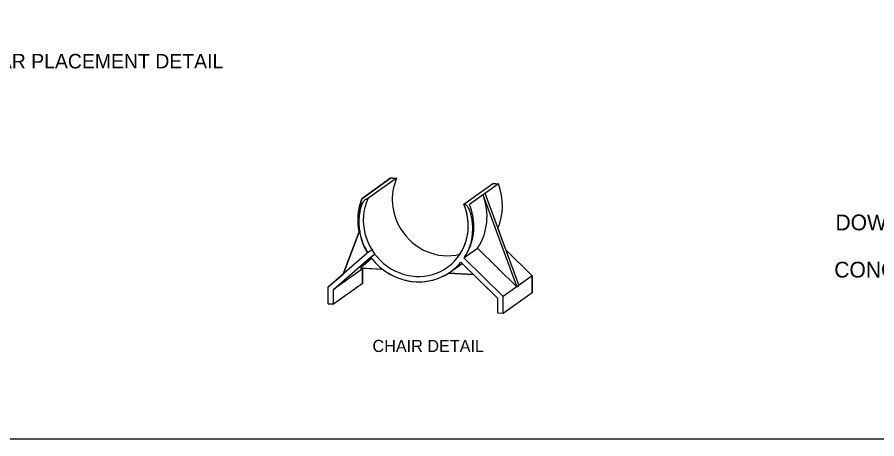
# Model space of a CAD drawing. Extents: x 99862 to 104211, y 98939 to 105076.
# Drawn here: x 101295 to 102716, y 103000 to 103696 of the extents above; entities that cross this region are included whole.
import ezdxf

# ---------------------------------------------------------------- set-up
doc = ezdxf.new("R2010")
doc.units = 0
for name, color, linetype in [('Level 1', 7, 'Continuous'), ('Level 15', 7, 'Continuous'), ('Level 16', 7, 'Continuous'), ('Level 20', 7, 'Continuous'), ('Level 62', 7, 'Continuous')]:
    doc.layers.add(name, color=color, linetype=linetype)

msp = doc.modelspace()

# ---------------------------------------------------------------- linework, layer by layer
at = {"layer": 'Level 1'}
msp.add_lwpolyline([(99862, 102999.5), (103151, 102999.5), (103151, 105075.5), (99862, 105075.5)], close=True, dxfattribs=at)
at = {"layer": 'Level 15'}
msp.add_line((102121.2, 103250.4), (102124.4, 103252.7), dxfattribs=at)
at = {"layer": 'Level 16'}
for p, q in [((101913.2, 103430.3), (101865.3, 103396)), ((101922.6, 103429.8), (101874.7, 103395.5)), ((102033.7, 103386.8), (102081.6, 103421.1)), ((102091, 103420.6), (102043.1, 103386.3)), ((102069, 103403.8), (102124.4, 103252.7)), ((102065.8, 103401.5), (102121.2, 103250.4)), ((101860.7, 103341.5), (101834, 103271.5)), ((101809.6, 103250.2), (101874.5, 103306.9)), ((101874.5, 103306.9), (101881.5, 103311.8)), ((101879.6, 103299.4), (101886.6, 103304.3)), ((102033.9, 103298.2), (102056.3, 103314.2)), ((102121.2, 103250.4), (102056.3, 103314.2)), ((102146.7, 103268.7), (102102.6, 103312)), ((101818.3, 103245.8), (101879.6, 103299.4)), ((101881.3, 103297.3), (101862.6, 103281)), ((102011.8, 103275.4), (102031, 103289.1)), ((102090.1, 103231), (102028.8, 103291.3)), ((102098.8, 103234.5), (102033.9, 103298.2)), ((101866.2, 103280.1), (101818.3, 103245.8)), ((101900, 103279), (101862.6, 103281)), ((101866.2, 103280.1), (101867, 103280.8)), ((101866.2, 103256), (101866.2, 103280.1)), ((102008.5, 103273.1), (102049.6, 103270.8)), ((102146.7, 103268.7), (102098.8, 103234.5)), ((102146.7, 103240.7), (102146.7, 103268.7)), ((101809.6, 103222.3), (101809.6, 103250.2)), ((101866.2, 103256), (101818.3, 103221.8)), ((101818.3, 103221.8), (101818.3, 103245.8)), ((102146.7, 103240.7), (102098.8, 103206.5)), ((102098.8, 103206.5), (102098.8, 103234.5)), ((101809.6, 103222.3), (101818.3, 103221.8)), ((102090.1, 103207), (102090.1, 103231)), ((102098.8, 103206.5), (102090.1, 103207))]:
    msp.add_line(p, q, dxfattribs=at)
for points in [[(101865.3, 103396), (101913.2, 103430.3)], [(102033.7, 103386.8), (102081.6, 103421.1)], [(102089.8, 103347), (102102.6, 103312), (102146.7, 103268.7), (102146.7, 103240.7), (102098.8, 103206.5), (102090.1, 103207), (102090.1, 103231), (102049.6, 103270.8), (102008.5, 103273.1)], [(101900, 103279), (101867, 103280.8), (101866.2, 103280.1), (101866.2, 103256), (101818.3, 103221.8), (101809.6, 103222.3), (101809.6, 103250.2), (101834, 103271.5), (101860.7, 103341.5)]]:
    msp.add_lwpolyline(points, dxfattribs=at)
for centre, major_axis, start_param, end_param in [((102002.1, 103390.1), (52.3, -73.2), 3.653116, 4.644013), ((102002.1, 103390.1), (52.3, -73.2), 3.653116, 4.644013), ((102002.1, 103390.1), (57.6, -80.5), 0.51692, 1.295209), ((102002.1, 103390.1), (57.6, -80.5), 0.51692, 1.295209), ((101979.8, 103374.2), (-57.6, 80.5), 4.428217, 4.436802), ((101954.2, 103355.9), (-52.3, 73.2), 0.511524, 4.47615), ((101976.6, 103371.9), (-57.6, 80.5), 3.485253, 4.436802), ((101954.2, 103355.9), (-52.3, 73.2), 3.495016, 4.47615), ((102002.1, 103390.1), (52.3, -73.2), 4.644013, 5.929762), ((102002.1, 103390.1), (52.3, -73.2), 4.644013, 5.929762), ((101976.6, 103371.9), (-57.6, 80.5), 3.482403, 3.485253), ((101954.2, 103355.9), (-57.6, 80.5), 1.596779, 3.390895), ((101954.2, 103355.9), (-57.6, 80.5), 1.88936, 3.098314)]:
    msp.add_ellipse(centre, major_axis=major_axis, ratio=0.944998, start_param=start_param, end_param=end_param, dxfattribs=at)
for points, degree in [([(101913.2, 103430.3), (101913.2, 103430.3), (101913.2, 103430.3), (101917.9, 103430), (101922.6, 103429.8)], 4), ([(101913.2, 103430.3), (101917.9, 103430), (101922.6, 103429.8)], 2), ([(102081.6, 103421.1), (102086.3, 103420.8), (102091, 103420.6)], 2), ([(102081.6, 103421.1), (102086.3, 103420.8), (102091, 103420.6)], 2), ([(101859.2, 103370.2), (101860.5, 103383.7), (101865.3, 103396)], 2), ([(101865.3, 103396), (101865.3, 103396), (101865.3, 103396), (101847.4, 103350.3), (101874.5, 103306.9)], 4), ([(101874.5, 103306.9), (101847.4, 103350.3), (101865.3, 103396), (101870, 103395.8), (101874.7, 103395.5)], 4), ([(102033.7, 103386.8), (102038.4, 103386.6), (102043.1, 103386.3), (102061.1, 103338.6), (102033.9, 103298.2)], 4), ([(102033.9, 103298.2), (102061.1, 103338.6), (102043.1, 103386.3)], 2), ([(101860.7, 103341.5), (101857.9, 103355.9), (101859.2, 103370.2)], 2)]:
    msp.add_open_spline(points, degree=degree, dxfattribs=at)

# ---------------------------------------------------------------- texts
at = {"layer": 'Level 20'}
for s, height, p in [('DOWEL BAR PLACEMENT DETAIL', 24, (101117.1, 103611.1)), ('CHAIR DETAIL', 20, (101882.7, 103142.8))]:
    msp.add_text(s, height=height, dxfattribs=at).set_placement(p)
at = {"layer": 'Level 62'}
for s, p in [('DOWEL BAR RETROFIT', (102647.9, 103343.8)), ('CONCRETE PAVEMENT', (102645.9, 103265.8))]:
    msp.add_text(s, height=26, dxfattribs=at).set_placement(p)

doc.saveas('drawing.dxf')
